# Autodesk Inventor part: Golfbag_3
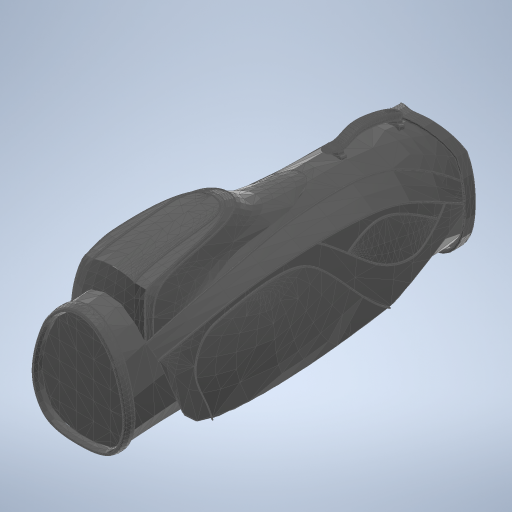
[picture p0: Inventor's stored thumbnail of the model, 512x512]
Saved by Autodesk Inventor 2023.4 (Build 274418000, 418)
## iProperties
Created: 2025-03
Part Number: Golfbag_3
Material: Générique
Document SubType Name: Modeling
Designer: bruno
Density: 1 g/cm^3
Appearance: Par défaut
Author: bruno
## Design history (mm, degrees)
node "Golfbag__3"
  node "FonctionMaillage1"
